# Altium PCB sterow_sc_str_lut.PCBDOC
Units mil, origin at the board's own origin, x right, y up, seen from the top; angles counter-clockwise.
Board outline 6010 x 6345 mil, 2 copper layers (Top Layer, Bottom Layer); 70 components, 89 nets, 354 pads, 50 vias.
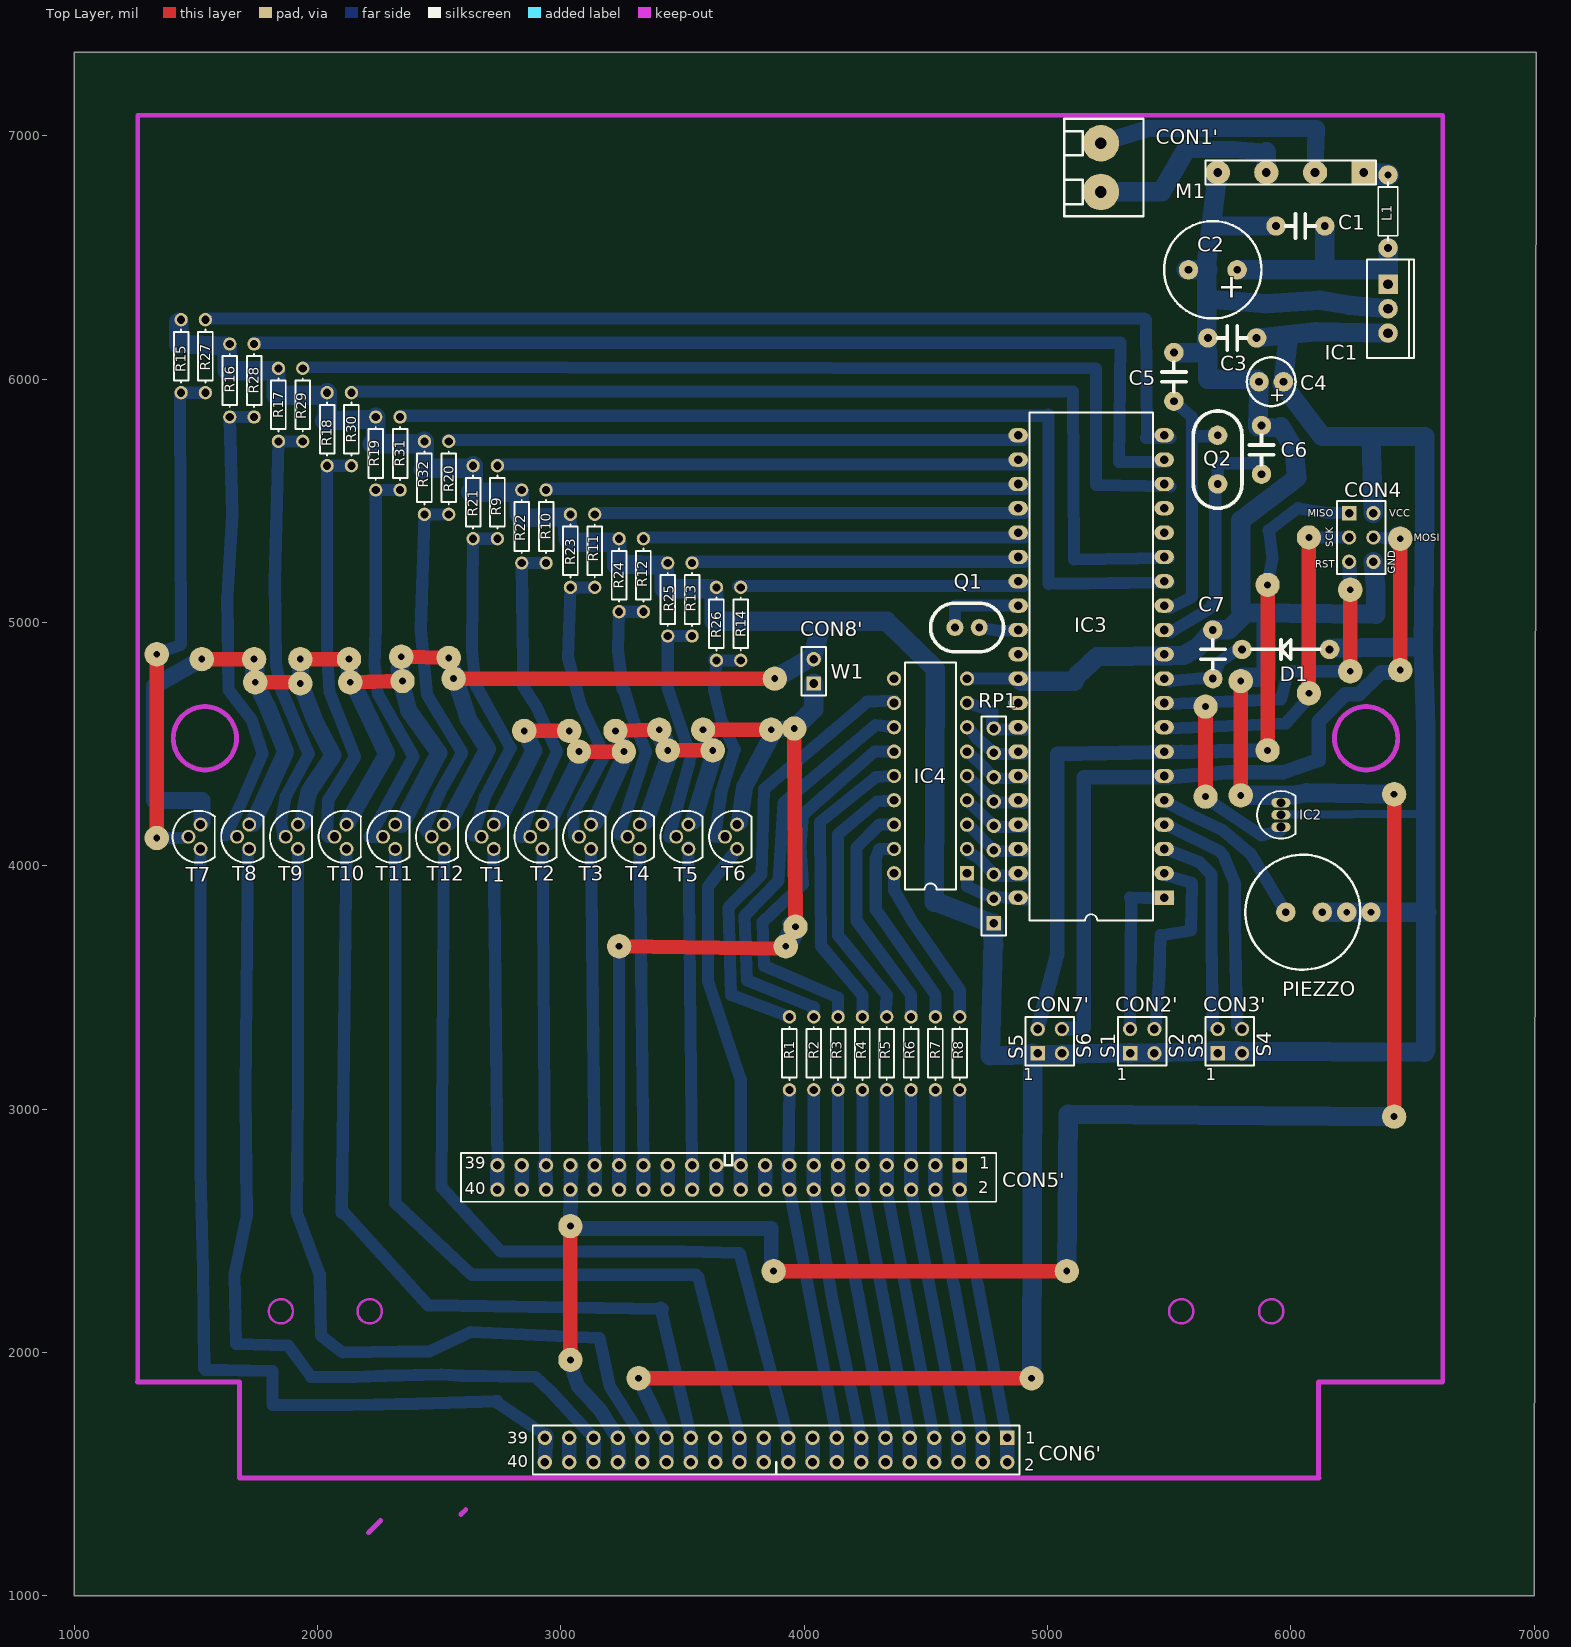
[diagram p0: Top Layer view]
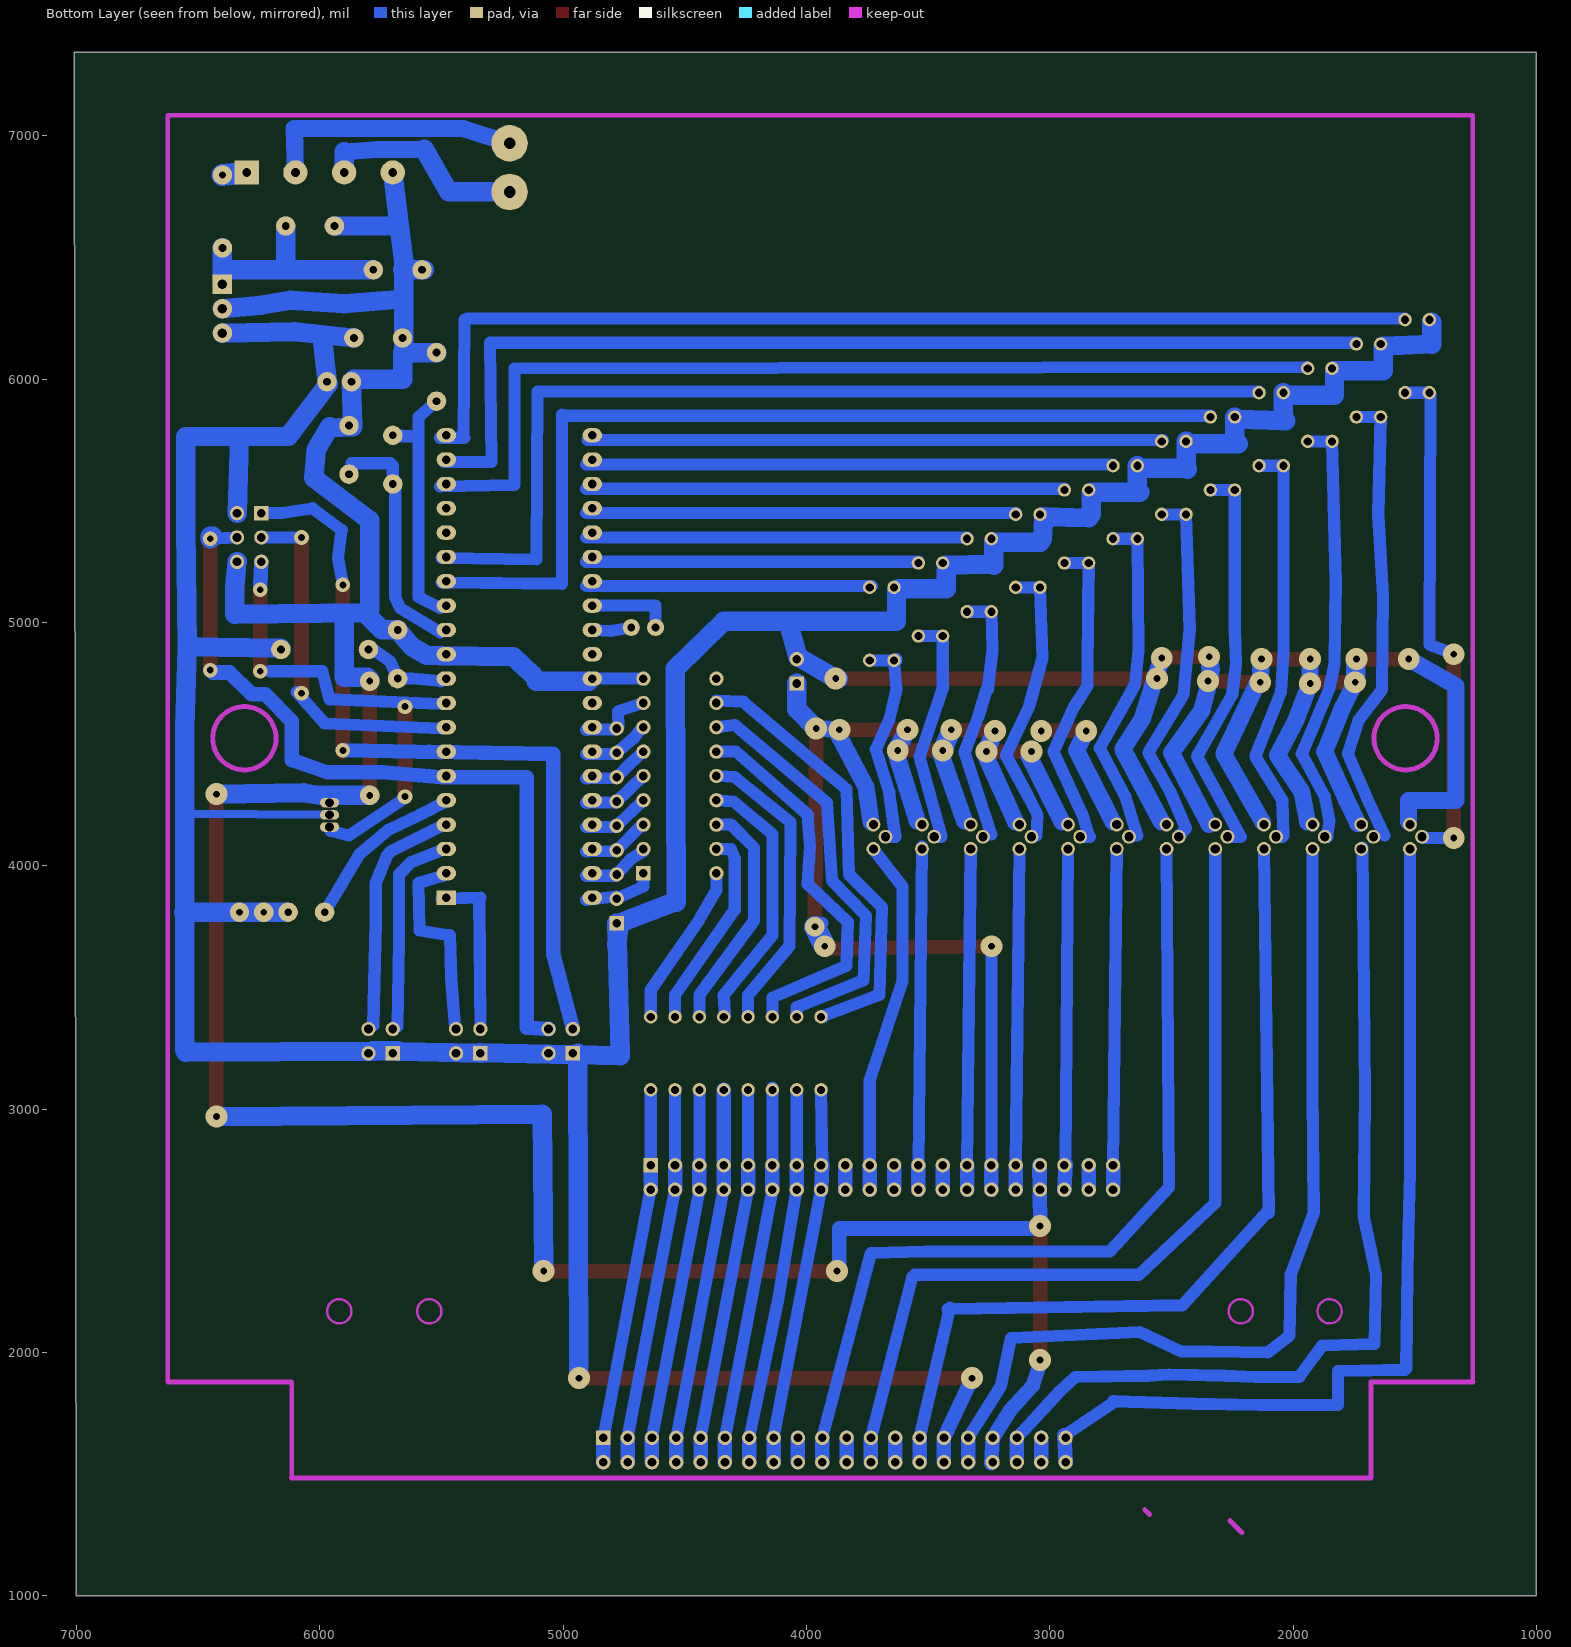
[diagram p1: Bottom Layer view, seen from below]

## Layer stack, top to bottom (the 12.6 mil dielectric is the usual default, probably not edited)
Top Layer: signal copper 1.4
Dielectric: dielectric 12.6, FR-4, Dk 4.8
Bottom Layer: signal copper 1.4

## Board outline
1000,1000 7000,1000 7010,7345 1000,7345

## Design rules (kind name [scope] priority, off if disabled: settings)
Clearance [All] p1: gap=10
ComponentClearance [All] p1: gap=1 collisioncheckmode=0
PolygonConnect [All] p1: connectstyle=Relief reliefconductorwidth=10 reliefentries=4 polygonreliefangle="90 Angle"
RoutingLayers [All] p1: top layer=Horizontal bottom layer=Vertical
RoutingVias [All] p1: holewidth=28 width=50 viastyle="Through Hole" minholewidth=28 minwidth=50 maxholewidth=28 maxwidth=50
SolderMaskExpansion [All] p1: expansion=4
TestPointUsage [All] p1: valid=0 allowmultiple=FALSE
Testpoint [All] p1: side=15 testpointundercomponent=TRUE minsize=40 maxsize=100 preferedsize=60 minholesize=0 maxholesize=40 preferedholesize=32 testpointgrid=1 style=1023 order=-539222988
Width [All] p1: maxlimit=90 minlimit=10 preferedwidth=10 toplayer_prefwidth=50 bottomlayer_prefwidth=80 minimp=50.000000 maximp=50.000000 favimp=50.000000
16 further rules are at their usual default settings.

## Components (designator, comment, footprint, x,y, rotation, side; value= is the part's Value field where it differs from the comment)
C1 "100nF" C2 6040,6630 r0 top
C2 "1000uF" CE10 5680,6450 r180 top
C3 "100nF" C2 5760,6170 r0 top
C4 "100uF" CE5 5920,5990 r180 top
C5 "27p" C2 5520,6010 r270 top
C6 "27p" C2 5880,5710 r270 top
C7 "100nF" C2 5680,4870 r270 top
CON1' "" ARK2 5220,6870 r90 top
CON2' "" HDR2X2 5340,3230 r0 top
CON3' "" HDR2X2 5700,3230 r0 top
CON4 "ISP" "HDR2X3_CEN - DUPLICATE" 6240,5450 r270 top
CON5' "Header 20X2" HDR2X20 4640,2770 r180 top
CON6' "Header 20X2" HDR2X20 4835,1650 r180 top
CON7' "" HDR2X2 4960,3230 r0 top
CON8' "Header 2" HDR1X2 4040,4750 r90 top
D1 "1N4148" D4 5980,4890 r180 top
IC1 "7805" 221A-04 6400,6290 r270 top
IC2 "DS1813" TO-92 5960,4210 r0 top
IC3 "ATmega8535" 40P6 5180,4820 r90 top
IC4 "ULN2803" DIP-18 4520,4370 r90 top
L1 "22uH" AXIAL-0.3#1 6400,6690 r90 top
M1 "Bridge1" HDR1X7 6300,6850 r180 top
PIEZZO "" PIEZO 5980,3810 r0 top (schematic designator Q3)
Q1 "32768Hz" X1 4620,4980 r180 top
Q2 "8MHz" X2 5700,5670 r90 top
R1 "Res2" AXIAL-0.3#2 3940,3230 r90 top
R2 "Res2" AXIAL-0.3#2 4040,3230 r90 top
R3 "Res2" AXIAL-0.3#2 4140,3230 r90 top
R4 "Res2" AXIAL-0.3#2 4240,3230 r90 top
R5 "Res2" AXIAL-0.3#2 4340,3230 r90 top
R6 "Res2" AXIAL-0.3#2 4440,3230 r90 top
R7 "Res2" AXIAL-0.3#2 4540,3230 r90 top
R8 "Res2" AXIAL-0.3#2 4640,3230 r90 top
R9 "Res2" AXIAL-0.3#2 2740,5495 r270 top
R10 "Res2" AXIAL-0.3#2 2940,5395 r270 top
R11 "Res2" AXIAL-0.3#2 3140,5295 r270 top
R12 "Res2" AXIAL-0.3#2 3340,5195 r270 top
R13 "Res2" AXIAL-0.3#2 3540,5095 r270 top
R14 "Res2" AXIAL-0.3#2 3740,4995 r270 top
R15 "3,3K" AXIAL-0.3#2 1440,6095 r90 top
R16 "3,3K" AXIAL-0.3#2 1640,5995 r90 top
R17 "3,3K" AXIAL-0.3#2 1840,5895 r90 top
R18 "3,3K" AXIAL-0.3#2 2040,5795 r90 top
R19 "3,3K" AXIAL-0.3#3 2240,5695 r90 top
R20 "3,3k" AXIAL-0.3#2 2540,5595 r270 top
R21 "Res2" AXIAL-0.3#2 2640,5495 r90 top
R22 "Res2" AXIAL-0.3#2 2840,5395 r90 top
R23 "Res2" AXIAL-0.3#2 3040,5295 r90 top
R24 "Res2" AXIAL-0.3#2 3240,5195 r90 top
R25 "Res2" AXIAL-0.3#2 3440,5095 r90 top
R26 "Res2" AXIAL-0.3#2 3640,4995 r90 top
R27 "3,3K" AXIAL-0.3#2 1540,6095 r270 top
R28 "3,3K" AXIAL-0.3#2 1740,5995 r270 top
R29 "3,3K" AXIAL-0.3#2 1940,5895 r270 top
R30 "3,3K" AXIAL-0.3#2 2140,5795 r270 top
R31 "3,3K" AXIAL-0.3#2 2340,5695 r270 top
R32 "3,3K" AXIAL-0.3#2 2440,5595 r90 top
RP1 "8x10K" HDR1X9 4780,3765 r90 top
T1 "BC557" TO92 2725,4070 r180 top
T2 "BC557" TO92 2925,4070 r180 top
T3 "*" TO92 3125,4070 r180 top
T4 "BC557" TO92 3325,4070 r180 top
T5 "BC557" TO92 3525,4070 r180 top
T6 "BC557" TO92 3725,4070 r180 top
T7 "BC557" TO92 1520,4070 r180 top
T8 "BC557" TO92 1720,4070 r180 top
T9 "BC557" TO92 1920,4070 r180 top
T10 "BC557" TO92 2120,4070 r180 top
T11 "BC557" TO92 2320,4070 r180 top
T12 "BC557" TO92 2520,4070 r180 top

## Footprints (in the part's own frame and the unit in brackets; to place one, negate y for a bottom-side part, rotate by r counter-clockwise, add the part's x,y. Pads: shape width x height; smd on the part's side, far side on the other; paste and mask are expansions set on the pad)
40P6 [mm]
  rect 1.5x2.032 hole 0.9: 1(-24.13,-7.62)
  oval 1.5x2.032 hole 0.9: 2(-21.59,-7.62) 3(-19.05,-7.62) 4(-16.51,-7.62) 5(-13.97,-7.62) 6(-11.43,-7.62) 7(-8.89,-7.62) 8(-6.35,-7.62) 9(-3.81,-7.62) 10(-1.27,-7.62) 11(1.27,-7.62) 12(3.81,-7.62) 13(6.35,-7.62) 14(8.89,-7.62) 15(11.43,-7.62) 16(13.97,-7.62) 17(16.51,-7.62) 18(19.05,-7.62) 19(21.59,-7.62) 20(24.13,-7.62) 21(24.13,7.62) 22(21.59,7.62) 23(19.05,7.62) 24(16.51,7.62) 25(13.97,7.62) 26(11.43,7.62) 27(8.89,7.62) 28(6.35,7.62) 29(3.81,7.62) 30(1.27,7.62) 31(-1.27,7.62) 32(-3.81,7.62) 33(-6.35,7.62) 34(-8.89,7.62) 35(-11.43,7.62) 36(-13.97,7.62) 37(-16.51,7.62) 38(-19.05,7.62) 39(-21.59,7.62) 40(-24.13,7.62)
  silkscreen extent -26.5,-6.45 26.5,6.45
221A-04 [mil]
  rect 80x80 hole 39.37: 1(-100,0)
  round 80 hole 39.37: 2(0,0) 3(100,0)
  silkscreen extent -203,-87 203,106
ARK2 [mil]
  round 150 hole 48: 1(-100,0) 2(100,0)
  silkscreen extent -200,-175 200,150
AXIAL-0.3#1 [mil]
  round 80 hole 33.47: 1(-150,0)
  round 80 hole 28: 2(150,0)
  silkscreen extent -120,-40 120,40
AXIAL-0.3#2 [mil]
  round 55.12 hole 33.46: 1(-150,0) 2(150,0)
  silkscreen extent -109,-30 109,30
AXIAL-0.3#3 [mil]
  round 55.12 hole 33.46: 1(-150,0)
  round 55.12 hole 33.47: 2(150,0)
  silkscreen extent -109,-30 109,30
C2 [mil]
  round 80 hole 32: 1(-100,0) 2(100,0)
  silkscreen extent -60,-50 60,50
CE5 [mil]
  round 80 hole 32: 1(-50,0) 2(50,0)
  silkscreen extent -100,-100 100,100
CE10 [mil]
  round 80 hole 32: 1(-100,0) 2(100,0)
  silkscreen extent -200,-200 200,200
D4 [mil]
  round 80 hole 32: 1(-180,0) 2(180,0)
  silkscreen extent -140,-40 140,40
DIP-18 [mm]
  rect 1.5x1.5 hole 0.9: 1(-10.16,-3.81)
  round 1.5 hole 0.9: 2(-7.62,-3.81) 3(-5.08,-3.81) 4(-2.54,-3.81) 5(0,-3.81) 6(2.54,-3.81) 7(5.08,-3.81) 8(7.62,-3.81) 9(10.16,-3.81) 10(10.16,3.81) 11(7.62,3.81) 12(5.08,3.81) 13(2.54,3.81) 14(0,3.81) 15(-2.54,3.81) 16(-5.08,3.81) 17(-7.62,3.81) 18(-10.16,3.81)
  silkscreen extent -11.85,-2.65 11.85,2.65
HDR1X2 [mm]
  rect 1.5x1.5 hole 0.9: 1(0,0)
  round 1.5 hole 0.9: 2(2.54,0)
  silkscreen extent -1.27,-1.27 3.81,1.27
HDR1X7 [mm]
  rect 2.54x2.54 hole 0.9: 1(0,0)
  round 2.54 hole 0.9: 2(5.08,0) 3(10.16,0) 4(15.24,0)
  silkscreen extent -1.27,-1.27 16.51,1.27
HDR1X9 [mm]
  rect 1.5x1.5 hole 0.9: 1(0,0)
  round 1.5 hole 0.9: 2(2.54,0) 3(5.08,0) 4(7.62,0) 5(10.16,0) 6(12.7,0) 7(15.24,0) 8(17.78,0) 9(20.32,0)
  silkscreen extent -1.27,-1.27 21.59,1.27
HDR2X2 [mm]
  rect 1.5x1.5 hole 0.9: 1(0,0)
  round 1.5 hole 0.9: 2(0,2.54) 3(2.54,0) 4(2.54,2.54)
  silkscreen extent -1.27,-1.27 3.81,3.81
"HDR2X3_CEN - DUPLICATE" [mm]
  rect 1.5x1.5 hole 0.9: 1(0,0)
  round 1.5 hole 0.9: 2(2.54,0) 3(5.08,0) 4(5.08,2.54) 5(2.54,2.54) 6(0,2.54)
  silkscreen extent -1.27,-1.27 6.35,3.81
HDR2X20 [mm]
  rect 1.5x1.5 hole 0.9: 1(0,0)
  round 1.5 hole 0.9: 2(0,2.54) 3(2.54,0) 4(2.54,2.54) 5(5.08,0) 6(5.08,2.54) 7(7.62,0) 8(7.62,2.54) 9(10.16,0) 10(10.16,2.54) 11(12.7,0) 12(12.7,2.54) 13(15.24,0) 14(15.24,2.54) 15(17.78,0) 16(17.78,2.54) 17(20.32,0) 18(20.32,2.54) 19(22.86,0) 20(22.86,2.54) 21(25.4,0) 22(25.4,2.54) 23(27.94,0) 24(27.94,2.54) 25(30.48,0) 26(30.48,2.54) 27(33.02,0) 28(33.02,2.54) 29(35.56,0) 30(35.56,2.54) 31(38.1,0) 32(38.1,2.54) 33(40.64,0) 34(40.64,2.54) 35(43.18,0) 36(43.18,2.54) 37(45.72,0) 38(45.72,2.54) 39(48.26,0) 40(48.26,2.54)
  silkscreen extent -3.81,-1.27 52.07,3.81
PIEZO [mil]
  round 80 hole 32: 1(0,0) 2(150,0)
  silkscreen extent -166,-236 306,236
TO92 [mil]
  round 57 hole 38: 1(0,0) 2(50,-50) 3(0,-100)
  silkscreen extent -59,-157 115,57
TO-92 [mm]
  oval 2x1 hole 0.9: 1(0,-1.27) 2(0,0) 3(0,1.27)
  silkscreen extent -2.48,-2.48 1.5,2.48
X1 [mil]
  round 70 hole 32: 1(0,0) 2(-100,0)
  silkscreen extent -200,-100 100,100
X2 [mil]
  round 80 hole 32: 1(100,0) 2(-100,0)
  silkscreen extent -200,-100 200,100

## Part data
C1 C3 C5 C6 C7: library part C, "Kondensator"
C2 C4: library part EL, "Elektrolit"
CON1': library part "Header 2", "Header, 2-Pin"
CON2' CON3' CON7': library part "Header 2X2", "Header, 2-Pin, Dual row"
CON4: library part "Header 3X2_ISP", "Header, 3-Pin, Dual row"
CON5': "Header, 20-Pin, Dual row"
CON6': library part "Edge Con 22", "22-Pin Edge Connector"
CON8': "Header, 2-Pin"
D1: library part D, "Dioda"
IC1: library part MC7805ACT, "3-Terminal Positive Fixed Voltage Regulator"
IC2: library part DS1813-10, "5V EconoReset with Pushbutton"
IC3: library part ATmega8535-16PU, "8-Bit AVR Microcontroller with 8K Bytes of In-System Programmable Flash Memory"
IC4: library part ULN2803A, "Octal Peripheral Driver Array"
M1: "Full Wave Diode Bridge"
PIEZZO: library part PIEZO, "Loudspeaker"
Q1 Q2: library part CRYSTAL_1, "rezonator"
R1 R2 R3 R4 R5 R6 R7 R8 R9 R10 R11 R12 R13 R14 R21 R22 R23 R24 R25 R26: "Resistor"
R15 R16 R17 R18 R19 R20 R27 R28 R29 R30 R31 R32: library part Res2, "Resistor"
RP1: library part "Res Pack4", "Resistor Array"
T1 T2 T4 T5 T6 T7 T8 T9 T10 T11 T12: "Amplifier Transistor PNP Silicon"
T3: library part BC557, "Amplifier Transistor PNP Silicon"

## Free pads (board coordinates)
  round 100 smd: 0(1340,4115) 1(1340,4870) 3(5905,5155) 4(3240,3670) 4(3865,4560) 4(3960,4565) 4(5080,2335) 4(5905,4475) 5(3925,3670) 5(5650,4655) 6(5650,4285) 7(5795,4760) 8(5795,4290) 9(3040,2520) 9(4935,1895) 10(1525,4850) 10(3965,3750) 11(1740,4850) 12(1745,4755) 13(1930,4750) 14(1930,4850) 15(2135,4755) 15(3320,1895) 16(2130,4850) 16(3040,1970) 17(2350,4760) 18(2345,4860) 19(2560,4770) 20(2540,4855) 21(3880,4770) 22(3075,4470) 23(3260,4470) 24(3440,4475) 25(3405,4560) 26(3225,4555) 27(3035,4555) 27(6245,4800) 28(2850,4555) 28(6245,5135) 29(3625,4475) 29(6075,4710) 30(3585,4560) 30(6075,5350) 31(6450,5345) 32(6450,4805) 35(6425,4295) 36(6425,4295) 37(6425,2970) 38(6425,2970) 41(3875,2335)
  round 30 on Keep-Out: 0(2895,1340)

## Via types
v1: diameter 90, hole 28, Top Layer to Bottom Layer, 35 vias
v2: diameter 60, hole 28, Top Layer to Bottom Layer, 10 vias
v3: diameter 80, hole 28, Top Layer to Bottom Layer, 5 vias

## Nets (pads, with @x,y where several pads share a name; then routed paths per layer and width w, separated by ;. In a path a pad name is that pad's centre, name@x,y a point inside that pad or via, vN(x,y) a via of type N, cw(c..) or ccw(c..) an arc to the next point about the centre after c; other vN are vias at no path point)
A1': CON5'.39 CON5'.40 T1.1 | length 1400.1
  Bottom Layer w50: T1.1 CON5'.39
  Bottom Layer w60: CON5'.40 CON5'.39
A2': CON5'.35 CON5'.36 T2.1 | length 1400.2
  Bottom Layer w50: T2.1 CON5'.35@2935,2775
  Bottom Layer w60: CON5'.35@2935,2775 CON5'.36
A3': CON5'.31 CON5'.32 T3.1 | length 1400.1
  Bottom Layer w50: T3.1 CON5'.31
  Bottom Layer w60: CON5'.32 CON5'.31
A4': CON5'.27 CON5'.28 T4.1 | length 1400.1
  Bottom Layer w50: T4.1 CON5'.27
  Bottom Layer w60: CON5'.28 CON5'.27
A5': CON5'.23 CON5'.24 T5.1 | length 1410.1
  Bottom Layer w50: T5.1@3525,4080 CON5'.23
  Bottom Layer w60: CON5'.24 CON5'.23
A6': CON5'.19 CON5'.20 T6.1 | length 1462.7
  Bottom Layer w50: T6.1 3605,3915 3605,3530 3740,3120 CON5'.19
  Bottom Layer w60: CON5'.20 CON5'.19
A7': CON6'.39 CON6'.40 T7.1 | length 3837.9
  Bottom Layer w50: T7.1 1520,3535 1520,2745 1530,2340 1535,1935 ; 1540,1930 1815,1925 1815,1785 2140,1785 2410,1790 2740,1800 ; 2730,1800 CON6'.39@2940,1660
  Bottom Layer w60: CON6'.40 CON6'.39@2940,1660
A8': CON6'.35 CON6'.36 T8.1 | length 3778.4
  Bottom Layer w50: T8.1@1715,4075 1705,3070 1710,2565 1660,2320 1665,2035 1880,2030 1975,1900 2155,1900 2280,1905 2510,1910 2595,1905 2895,1900 2955,1845 CON6'.35
  Bottom Layer w60: CON6'.36@3135,1560 CON6'.35
A9': CON6'.31 CON6'.32 T9.1 | length 3757.7
  Bottom Layer w50: T9.1 1920,3080 1915,2575 2010,2320 2015,2070 2105,2000 2335,2005 2460,2005 2630,2085 3160,2060 3200,1865 CON6'.31
  Bottom Layer w60: CON6'.32 CON6'.31
A10': CON6'.27 CON6'.28 T10.1 | length 3637
  Bottom Layer w50: 2100,2575 T10.1 ; 2100,2585 2455,2195 3420,2180 ; 3410,2185 CON6'.27
  Bottom Layer w60: CON6'.28 CON6'.27
A11': CON6'.23 CON6'.24 T11.1 | length 3568.1
  Bottom Layer w50: 2320,2615 2635,2320 3555,2320 ; 2320,2620 T11.1@2320,4055 ; 3565,2310 CON6'.23
  Bottom Layer w60: CON6'.24 CON6'.23
A12': CON6'.19 CON6'.20 T12.1 | length 3611.9
  Bottom Layer w50: 2510,2680 2755,2415 3510,2415 3735,2410 CON6'.19 ; 2510,2685 T12.1
  Bottom Layer w60: CON6'.20 CON6'.19
A': CON5'.15 CON5'.16 CON6'.15 CON6'.16 R1.1 | length 1548.6
  Bottom Layer w50: CON5'.15@3935,2775 R1.1 ; CON5'.16 CON6'.15
  Bottom Layer w60: CON5'.15@3935,2775 CON5'.16 ; CON6'.16 CON6'.15
B': CON5'.13 CON5'.14 CON6'.13 CON6'.14 R2.1 | length 1548.7
  Bottom Layer w50: CON5'.14 4115,2225 CON6'.13 ; CON5'.13 R2.1
  Bottom Layer w60: CON5'.14 CON5'.13 ; CON6'.14 CON6'.13
C1: IC3.22 R9.1 | length 2165
  Bottom Layer w50: R9.1@2740,5650 IC3.22@4905,5650
C2: IC3.23 R10.1 | length 1965
  Bottom Layer w50: R10.1@2940,5550 IC3.23@4905,5550
C3: IC3.24 R11.1 | length 1765
  Bottom Layer w50: R11.1@3140,5450 IC3.24@4905,5450
C4: IC3.25 R12.1 | length 1565
  Bottom Layer w50: R12.1@3340,5350 IC3.25@4905,5350
C5: IC3.26 R13.1 | length 1365
  Bottom Layer w50: R13.1@3540,5250 IC3.26@4905,5250
C6: IC3.27 R14.1 | length 1175
  Bottom Layer w50: R14.1@3730,5150 IC3.27@4905,5150
C7: IC3.20 R27.1 | length 4440
  Bottom Layer w50: R27.1@1540,6250 5395,6250 ; 5405,5760 IC3.20@5505,5760 ; 5405,6245 5410,5760
C8: IC3.19 R28.1 | length 4235
  Bottom Layer w50: R28.1@1740,6150 5300,6150 5295,5660 ; 5305,5660 IC3.19@5490,5660
C9: IC3.18 R29.1 | length 4047.1
  Bottom Layer w50: R29.1 1945,6050 5200,6045 5200,5565 IC3.18@5505,5560
C10: IC3.15 R30.1 | length 4045.1
  Bottom Layer w50: R30.1@2140,5950 5105,5950 5110,5260 IC3.15@5500,5265
C11: IC3.14 R31.1 | length 3855
  Bottom Layer w50: R31.1@2340,5850 5005,5850 ; 5005,5855 5005,5160 IC3.14@5500,5165
C12: IC3.21 R20.1 | length 2365
  Bottom Layer w50: R20.1@2535,5750 IC3.21@4900,5750
C': CON5'.11 CON5'.12 CON6'.11 CON6'.12 R3.1 | length 1558.5
  Bottom Layer w50: CON5'.12 CON6'.11 ; CON5'.11 R3.1@4140,3090
  Bottom Layer w60: CON5'.12 CON5'.11 ; CON6'.12 CON6'.11
D': CON5'.9 CON5'.10 CON6'.9 CON6'.10 R4.1 | length 1548.5
  Bottom Layer w50: CON5'.10 CON6'.9 ; CON5'.9 R4.1
  Bottom Layer w60: CON5'.10 CON5'.9 ; CON6'.10 CON6'.9
DP': CON5'.1 CON5'.2 CON6'.1 CON6'.2 R8.1 | length 1548.5
  Bottom Layer w50: CON5'.2 CON6'.1 ; CON5'.1 R8.1
  Bottom Layer w60: CON5'.2 CON5'.1 ; CON6'.2 CON6'.1
E': CON5'.7 CON5'.8 CON6'.7 CON6'.8 R5.1 | length 1548.5
  Bottom Layer w50: CON5'.8 CON6'.7
  Bottom Layer w60: CON5'.8 R5.1 ; CON6'.8 CON6'.7
F': CON5'.5 CON5'.6 CON6'.5 CON6'.6 R6.1 | length 1548.5
  Bottom Layer w50: CON5'.6 CON6'.5 ; CON5'.5 R6.1
  Bottom Layer w60: CON5'.6 CON5'.5 ; CON6'.6 CON6'.5
G': CON5'.3 CON5'.4 CON6'.3 CON6'.4 R7.1 | length 1548.5
  Bottom Layer w50: CON5'.4 CON6'.3 ; CON5'.3 R7.1
  Bottom Layer w60: CON5'.4 CON5'.3 ; CON6'.4 CON6'.3
GND': C1.1 C2.2 C3.1 C4.2 C5.1 C6.1 C7.1 CON4.4 CON5'.33 CON5'.34 CON6'.33 CON6'.34 IC1.2 IC2.3 IC3.11 IC3.31 IC4.9 M1.4 pad.4@5080,2335 pad.7 pad.8 pad.9@3040,2520 pad.16@3040,1970 pad.35 pad.36 pad.37 pad.38 pad.41 | length 13655.8
  Top Layer w60: v1(3040,1970) v1(3040,2520) ; v1(3875,2335) v1(5080,2335) ; v3(5795,4290) v3(5795,4760) ; v1(6425,2970) v1(6425,4295)
  Bottom Layer w50: IC4.9 IC3.31@4895,4770 ; C4.2@5860,6000 C4.2
  Bottom Layer w60: v1@3035,1970 3070,1865 3165,1760 CON6'.33 CON6'.34@3240,1545 ; v1@3040,2510 3865,2510 v1@3865,2340 ; v1(3040,2520) 3041.3,2669.99 CON5'.33@3042.17,2769.98
  Bottom Layer w80: IC3.31@4895,4760 5110,4760 ; v1@5080,2345 5085,2980 v1(6425,2970) ; 5125,4785 5205,4860 IC3.11@5500.01,4864.16 ; IC3.11@5504.94,4864.22 5560,4865 5620,4900 C7.1 5745,4970 5815,5040 6350,5035 6350,5145 CON4.4 ; C5.1 5660,6110 5660,6000 C4.2@5860,6000 ; C2.2@5570,6450 5660,6450 ; 5655,6105 5655,6485 5672.88,6630 ; 5655,6330 5900,6310 6120,6325 6240,6305 IC1.2 ; M1.4 5672.88,6630 ; v3(5795,4290) 5980,4290 ; v3@5795,4765 5805,4775 5900,4775 5900,5005 ; 5795,5055 5795,5420 6025,5595 6015,5710 5960,5805 ; C4.2 5865.15,5810.4 5865,5805 5955,5800 ; C1.1 5672.88,6630 ; 6000,4290 6065,4300 v1(6425,4295)
MISO: CON4.1 CON7'.2 IC3.7 pad.3 pad.4@5905,4475 | length 3325
  Top Layer w60: pad.4@5905,4470 v2(5905,5155)
  Bottom Layer w50: IC3.7@5495,4465 5499.83,4465.9 IC3.7@5503.77,4466.62 ; v2(5905,5155) 5925,5265 5910,5380 6030,5470 6155,5450 CON4.1
  Bottom Layer w60: CON7'.2 5040,3635 5040,4460 5550,4470 ; IC3.7@5503.77,4466.62 v2@5895,4475
  other v2: 5905,4475
MOSI: CON4.5 CON7'.4 IC3.6 pad.31 pad.32 | length 3336.4
  Top Layer w60: v2(6450,4805) v2(6450,5345)
  Bottom Layer w50: CON4.5 v2(6450,5345)
  Bottom Layer w60: CON7'.4 5150,3335 5150,3855 5150,4365 5500,4365 5740,4385 5970,4385 6115,4435 6115,4595 6225,4705 6280,4705 6370,4795 v2@6440,4795
  Bottom Layer w80: v2(6450,5345) 6440,5355 v2@6450,5355
NC1': CON5'.37 CON5'.38 | length 100
  Bottom Layer w60: CON5'.38 CON5'.37
NC2': CON5'.25 CON5'.26 | length 100
  Bottom Layer w60: CON5'.26 CON5'.25
NC3': CON5'.21 CON5'.22 | length 100
  Bottom Layer w60: CON5'.22 CON5'.21
NC4': CON5'.17 CON5'.18 | length 100
  Bottom Layer w60: CON5'.18 CON5'.17
NC5': CON6'.37 CON6'.38 | length 100
  Bottom Layer w60: CON6'.38 CON6'.37
NC6': CON6'.25 CON6'.26 | length 100
  Bottom Layer w60: CON6'.26 CON6'.25
NC7': CON6'.21 CON6'.22 | length 100
  Bottom Layer w60: CON6'.22 CON6'.21
NC8': CON6'.17 CON6'.18 | length 100
  Bottom Layer w60: CON6'.18 CON6'.17
NetC1_2: C1.2 C2.1 IC1.1 L1.1 | length 945
  Bottom Layer w80: C2.1 6400,6450 ; 6140,6455 C1.2 ; IC1.1 L1.1
NetCON1'_1: CON1'.1 M1.3 | length 866.9
  Bottom Layer w70: 5570,6945 5765,6945 5900,6935
  Bottom Layer w80: CON1'.1 5470,6770 5570,6945 ; M1.3 5900,6935
NetCON1'_2: CON1'.2 M1.2 | length 1074.3
  Bottom Layer w70: CON1'.2 5410,7030 6105,7030 M1.2
NetIC4_11: IC4.11 R1.2 | length 1844.6
  Bottom Layer w50: IC4.11@4370,4680 4260,4675 3835,4315 3825,3965 3690,3830 3700,3470 R1.2 ; R1.2 3930,3380 R1.2
NetIC4_12: IC4.12 R2.2 | length 1696
  Bottom Layer w50: R2.2 4040,3420 3765,3530 3755,3795 3895,3940 3915,4260 4295,4580 IC4.12
NetIC4_13: IC4.13 R3.2 | length 1576.9
  Bottom Layer w50: R3.2 4140,3460 3835,3590 3830,3770 3995,3925 3985,4080 3995,4210 4290,4470 IC4.13
NetIC4_14: IC4.14 R4.2 | length 1207.9
  Bottom Layer w50: 4065,4165 4070,3670 4240,3470 R4.2 ; 4065,4180 4295,4365 IC4.14@4360,4370
NetIC4_15: IC4.15 R5.2 | length 1103
  Bottom Layer w50: R5.2 4335,3385 4340,3470 4140,3715 4140,4130 4300,4265 IC4.15
NetIC4_16: IC4.16 R6.2 | length 963.4
  Bottom Layer w50: IC4.16 4310,4170 4215,4075 4215,3775 4440,3470 R6.2
NetIC4_17: IC4.17 R7.2 | length 809.9
  Bottom Layer w50: IC4.17@4360,4070 4310,4070 4295,4030 4295,3820 4540,3470 R7.2@4540,3390
NetIC4_18: IC4.18 R8.2 | length 671.2
  Bottom Layer w50: IC4.18 4370,3900 4440,3780 4640,3490 R8.2
NetL1_2: L1.2 M1.1 | length 100.5
  Bottom Layer w90: M1.1 L1.2
NetR9_2: R9.2 R21.1 T1.2 | length 1427.4
  Bottom Layer w50: T1.2 2640,4125 2690,4285 2795,4485 2650,4745 2635,4885 R21.1 R9.2
NetR10_2: R10.2 R22.1 T2.2 | length 1324.8
  Bottom Layer w50: 2835,4120 T2.2 ; 2840,4125 2865,4210 2905,4295 2985,4470 2900,4655 2845,4740 2845,4830 R22.1 R10.2
NetR11_2: R11.2 R23.1 T3.2 | length 1181.5
  Bottom Layer w50: T3.2@3055,4125 3050,4210 3085,4280 3180,4455 3085,4655 3030,4855 R23.1 R11.2
NetR12_2: R12.2 R24.1 T4.2 | length 1080.9
  Bottom Layer w50: 3255,4725 3235,4885 R24.1 R12.2 ; 3260,4725 3295,4610 3350,4470 ; T4.2 3240,4130 3350,4465
NetR13_2: R13.2 R25.1 T5.2 | length 962.1
  Bottom Layer w50: T5.2 3445,4120 3530,4430 ; 3535,4450 3440,4730 R25.1 R13.2
NetR14_2: R14.2 R26.1 T6.2 | length 876.3
  Bottom Layer w50: R26.1@3630,4850 R26.1@3630.09,4844.82 ; T6.2 3635,4120 3635,4120.28 3660,4305 3715,4480 3660,4600 3630,4725 R26.1 R14.2@3720,4845
NetR15_1: pad.0@1340,4115 pad.1 R15.1 R27.2 T7.2 | length 2132.5
  Top Layer w60: v1(1340,4115) v1(1340,4870)
  Bottom Layer w50: v1(1340,4115) 1465,4115 T7.2 ; v1(1340,4870) 1345,4875 1440,4910 1435,5940 R15.1 R27.2
NetR16_1: R16.1 R28.2 T8.2 | length 1899
  Bottom Layer w50: 1625,4125 1690,4265 1775,4460 1730,4600 1635,4725 1630,5110 1650,5445 R16.1 R28.2 ; T8.2@1662.92,4120 T8.2
NetR17_1: R17.1 R29.2 T9.2 | length 1787.6
  Bottom Layer w50: T9.2 1860,4120 1850,4185 1870,4285 1965,4460 1850,4730 1830,4830 1825,5165 R17.1 R29.2
NetR18_1: R18.1 R30.2 T10.2 | length 1703.5
  Bottom Layer w50: T10.2 2045,4120 2040,4125 2045,4270 2155,4450 2050,4715 2040,4870 2040,4975 R18.1 R30.2
NetR19_1: R19.1 R31.2 T11.2 | length 1665.2
  Bottom Layer w50: T11.2 2215,4120 2395,4450 2250,4705 2235,4830 2240,4975 R19.1 R31.2
NetR20_2: R20.2 R32.1 T12.2 | length 1515
  Bottom Layer w50: T12.2 2440,4155 2505,4305 2595,4465 2450,4705 2425,4970 R32.1 R20.2
OSC1: IC3.28 Q1.1 | length 350
  Bottom Layer w50: Q1.1 4620,5070 IC3.28
OSC2: IC3.29 Q1.2 | length 161.5
  Bottom Layer w50: Q1.2 4805,4965 IC3.29
PA0: IC3.40 IC4.1 RP1.2 | length 301.4
  Bottom Layer w50: IC4.1 4670,3915 4770,3870 4785,3875 IC3.40@4905,3860
PA1: IC3.39 IC4.2 RP1.3 | length 283.8
  Bottom Layer w50: IC4.2 4670,4060 4720,4030 RP1.3 4785,3960 IC3.39@4905,3960
PA2: IC3.38 IC4.3 RP1.4 | length 278.5
  Bottom Layer w50: IC4.3 4675,4170 RP1.4 ; RP1.4@4779.96,4061.34 4899.95,4060.05 IC3.38@4905,4060
PA3: IC3.37 IC4.4 RP1.5 | length 277.1
  Bottom Layer w50: IC4.4 RP1.5 ; RP1.5@4779.97,4161.11 4899.96,4160.04 IC3.37@4905,4160
PA4: IC3.36 IC4.5 RP1.6 | length 277.1
  Bottom Layer w50: IC4.5 RP1.6 ; RP1.6@4779.97,4260.94 4899.96,4260.04 IC3.36@4905,4260
PA5: IC3.35 IC4.6 RP1.7 | length 277.2
  Bottom Layer w50: IC4.6 4725,4420 RP1.7 ; RP1.7@4779.96,4361.63 4899.94,4360.07 IC3.35@4905,4360
PA6: IC3.34 IC4.7 RP1.8 | length 274.2
  Bottom Layer w50: IC4.7@4675,4570 4710,4525 RP1.8 ; RP1.8@4779.98,4460.72 4899.97,4460.03 IC3.34@4905,4460
PA7: IC3.33 IC4.8 RP1.9 | length 298.5
  Bottom Layer w50: IC4.8 4775,4635 RP1.9@4772.76,4572.24 ; RP1.9@4779.98,4560.65 4899.97,4560.03 IC3.33@4905,4560
PIEZO: IC3.5 PIEZZO.1 | length 687.1
  Bottom Layer w50: IC3.5@5490,4260 5590,4210 5715,4150 5835,4050 PIEZZO.1
RST: CON4.3 IC2.1 IC3.9 pad.5@5650,4655 pad.6 pad.27@6245,4800 pad.28@6245,5135 | length 1954.4
  Top Layer w60: v2(5650,4285) v2(5650,4655) ; v2(6245,4800) v2(6245,5135)
  Bottom Layer w50: IC3.9@5500,4665 5960,4685 5990,4800 6205,4800 ; v2@5650,4280 5880,4125 IC2.1@5955,4145
  Bottom Layer w60: CON4.3 v2@6245,5150
S1': CON2'.2 IC3.1 | length 702.2
  Bottom Layer w50: CON2'.2 5345,3865 5340,3870 IC3.1@5500,3865
S2': CON2'.4 IC3.2 | length 801.7
  Bottom Layer w50: CON2'.4@5445,3340 5460,3535 5465,3715 5590,3735 5595,3930 IC3.2@5495,3960
S3': CON3'.2 IC3.3 | length 830.4
  Bottom Layer w50: IC3.3@5500,4065 5625,4015 5675,3965 5675,3690 CON3'.2@5680,3340
S4': CON3'.4 IC3.4 | length 963.8
  Bottom Layer w50: IC3.4@5500,4165 5710,4060 5725,4040 5770,3930 5770,3770 CON3'.4@5780,3345
SCK: CON4.2 IC3.8 pad.29@6075,4710 pad.30@6075,5350 | length 1444
  Top Layer w60: v2(6075,4710) v2(6075,5350)
  Bottom Layer w50: IC3.8@5500,4565 5980,4585 v2@6095,4715 ; v2(6075,5350) CON4.2@6225,5350
VCC: CON5'.29 CON5'.30 CON8'.1 pad.4@3240,3670 pad.4@3865,4560 pad.4@3960,4565 pad.5@3925,3670 pad.10@3965,3750 pad.22 pad.23 pad.24 pad.25 pad.26 pad.27@3035,4555 pad.28@2850,4555 pad.29@3625,4475 pad.30@3585,4560 T1.3 T2.3 T3.3 T4.3 T5.3 T6.3 | length 6604.9
  Top Layer w60: v1(2850,4555) v1(3035,4555) ; v1(3075,4470) v1(3260,4470) ; v1(3225,4555) v1(3405,4560) ; v1(3240,3670) pad.5@3925,3660 ; v1(3440,4475) v1(3625,4475) ; v1(3585,4560) v1(3865,4560) ; v1(3960,4565) v3(3965,3750)
  Bottom Layer w50: CON5'.29 v1(3240,3670) ; v3@3935,3765 v3(3965,3750)
  Bottom Layer w60: CON5'.30 CON5'.29
  Bottom Layer w70: T1.3@2740,4180 2890,4475 v1(2850,4555) ; T2.3@2950,4180 3085,4450 v1(3075,4470) ; T3.3@3140,4180 3270,4465 v1(3225,4555) v1(3260,4470) ; 3350,4185 3450,4465 v1(3405,4560) ; T5.3@3545,4185 3635,4475 v1(3585,4560) v1(3625,4475) ; T6.3@3735,4180 3755,4325 3876.69,4553.78 v1@3880,4560 ; v1(3865,4560) v1(3960,4565)
  Bottom Layer w80: v1(3405,4560) v1(3440,4475) ; v1(3960,4565) 4040,4645 CON8'.1
  Bottom Layer w90: v1(3925,3670) v3(3965,3750)
VCC': C3.2 C4.1 CON2'.1 CON2'.3 CON3'.1 CON3'.3 CON4.6 CON6'.29 CON6'.30 CON7'.1 CON7'.3 CON8'.2 D1.1 IC1.3 IC2.2 pad.9@4935,1895 pad.10@1525,4850 pad.11 pad.12 pad.13 pad.14 pad.15 pad.16@2130,4850 pad.17 pad.18 pad.19 pad.20 pad.21 PIEZZO.2 R15.2 R16.2 R17.2 R18.2 R19.2 R21.2 R22.2 R23.2 R24.2 R25.2 R26.2 R32.2 RP1.1 T7.3 T8.3 T9.3 T10.3 T11.3 T12.3 | length 24632.2
  Top Layer w60: v1(1525,4850) v1(1740,4850) ; v1(1745,4755) pad.13@1925,4755 ; v1(1930,4850) v1(2130,4850) ; v1(2135,4755) v1(2350,4760) ; v1(2345,4860) v1(2540,4855) ; v1(2560,4770) v1(3880,4770) ; v1(3320,1895) v1(4935,1895)
  Bottom Layer w35: IC2.2 6555,4214.92
  Bottom Layer w50: R17.2@1830,6035 R17.2@1835,6040
  Bottom Layer w60: v1(3320,1895) CON6'.29 CON6'.30
  Bottom Layer w70: T7.3@1525,4180 1525,4270 1330,4270 1330,4740 v1(1525,4850) ; T8.3@1735,4175 1780,4270 1870,4470 1795,4655 v1(1745,4755) v1(1740,4850) ; T9.3@1940,4180 1965,4305 2065,4455 1990,4595 v1(1930,4750) ; T10.3@2125,4180 2285,4460 2135,4775 v1(2130,4850) 2135,4805 ; 2335,4805 v1(2345,4860) 2340,4770 2375,4640 2500,4465 T11.3@2345,4170 ; T12.3@2540,4180 2700,4480 2620,4605 v1(2540,4855) ; v1@3870,4770 v1(3880,4770) ; v1(1930,4750) v1(1930,4850) v1(1930,4750)
  Bottom Layer w80: R15.2@1430,6235 1430,6145 1630,6135 1630,6035 1830,6035 1830,5935 R18.2@2025,5935 ; v1(1740,4850) v1(1745,4755) ; 2030,5830 2039.99,5830.26 R19.2@2225,5835 ; 2040,5830 R18.2 ; 2225,5735 R32.2@2430,5735 ; 2235,5735 2240,5740 R19.2 ; 2435,5630 2440,5635 ; R32.2 2440,5635 ; 2630,5535 2830,5535 2830,5445 ; R21.2@2630,5635 2440,5635 ; 2640,5535 R21.2 ; 2840,5430 3025,5435 3030,5345 ; 3040,5330 3230,5330 3230,5235 ; 3245,5240 3425,5235 3425,5140 R26.2@3620,5140 ; 3630,5005 4340,5005 4540,4810 ; 3630,5015 R26.2@3630,5130 ; v1@3870,4770 v1(3880,4770) 4035,4860 4075,5000 ; 4535,3850 4540,4805 ; 4535,3855 4770,3765 4780,3675 ; 4765,3220 CON2'.1@5339.96,3232.86 ; 4765.15,3230.55 RP1.1 ; v1(4935,1895) CON7'.1@4940,3230 ; CON2'.1 CON3'.1@5679.89,3237.64 ; CON3'.1@5680,3240 CON3'.3@5779.98,3241.4 ; CON3'.3@5779.87,3239.04 6550,3235 ; C3.2 6105,6195 IC1.3 ; C4.1@5965,5980 6130,5765 6550,5765 6550,5395 6545,4900 ; C4.1 5990,6170 ; PIEZZO.2@6135,3810 6560,3810 ; D1.1@6159.94,4895.06 6545,4900 ; 6330,5765 CON4.6 ; 6555,3245 6555,4570 6545,4900
  other v3: 6230,3810 6330,3810
VCP: C7.2 D1.2 IC3.10 | length 340.2
  Bottom Layer w50: IC3.10@5502.64,4758.97 5505,4760 5620,4770 C7.2 5710,4840 D1.2@5780,4890
X1: C5.2 IC3.13 Q2.1 | length 1145
  Bottom Layer w50: IC3.13@5505,5060 5595,5105 5595,5765 ; C5.2 5595,5845 5595,5765 ; 5615,5765 Q2.1@5715,5765 ; Q2.1 5690,5770 5595,5765
X2: C6.2 IC3.12 Q2.2 | length 937.2
  Bottom Layer w50: IC3.12@5505,4960 5670,5060 5690,5105 Q2.2@5690,5565 ; Q2.2 5700,5645 ; 5710,5655 5870,5655
pads on no net: IC3.16 IC3.17 IC3.30 IC3.32 IC4.10

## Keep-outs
Keep-Out Layer:
  circle w10: c1850,2170 r50
  circle w10: c2215,2170 r50
  circle w10: c5550,2170 r50
  circle w10: c5920,2170 r50
  circle w20: c6310.04,4525 r130
  circle w20: c1537.64,4525 r130
  lines w10: 1675,1885 1680,1880
  lines w19.68: 1262.05,1880 1262.05,7084.96 6625,7085 ; 1680,1485 6116.38,1485 ; 6625,1880 6625,7084.96
  lines w20: 1260,1880 1680,1880 1680,1485 ; 2210,1260 2260,1310 ; 2590,1335 2610,1355 ; 6115,1485 6115,1880 6625,1880
  text "Rys.8b Uklad sciezek sterownika - strona lutowania" at 1410,1220 h120

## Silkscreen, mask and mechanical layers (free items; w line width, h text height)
Top Overlay:
  lines w10: 3675,2820 3675,2770 3690,2770 3705,2770 3705,2820 ; 3885,1500 3885,1550
  text "MISO" at 6070,5435 h30
  text "VCC" at 6405,5435 h30
  text "MOSI" at 6505,5335 h30
  text "SCK" at 6175,5310 h30 r90
  text "RST" at 6100,5225 h30
  text "GND" at 6430,5200 h30 r90
  text "W1" at 4110,4770 h60
  text "S4" at 5920,3215 h60 r90
  text "S6" at 5180,3210 h60 r90
  text "S1" at 5280,3210 h60 r90
  text "S2" at 5560,3210 h60 r90
  text "S3" at 5640,3210 h60 r90
  text "S5" at 4900,3205 h60 r90
Mechanical 4:
  lines w30: 5385,2345 5385,1980 6085,1980 6085,2350 5385,2350 ; 1690,1980 2390,1980 2390,2350 1690,2350 1690,1980
  lines w110: 5650,6965 6560,6965 ; 6565,6095 6565,6965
